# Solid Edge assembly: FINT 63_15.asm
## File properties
Title: Zylinder
Author: bmolnar
Template: iso assembly.asm
Last saved by: bmolnar
Revision: 11
Application: Solid Edge
Username: bmolnar
Dokumentum tartalom típus: 1
Document Number: FINT 63/15
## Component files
hrungsstange.par
Profilrohr.par
Platte.par
Kolbenstange.par
Kit_1.par
Kit_2.par
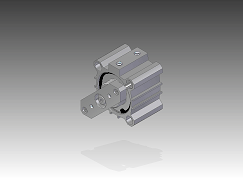
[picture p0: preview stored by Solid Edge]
